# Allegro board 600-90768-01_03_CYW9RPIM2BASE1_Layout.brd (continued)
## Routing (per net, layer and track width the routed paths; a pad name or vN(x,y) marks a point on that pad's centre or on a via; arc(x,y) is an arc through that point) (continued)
GND_EARTH: length 100.7
  BOTTOM w0.381: J47.SH3 44.82,85.98 ; J47.SH3 43.01,85.98 ; J47.SH3 43.91,87.39 ; J47.SH3 43.91,84.57 ; J3.SH2 70.69,77.65 ; J3.SH2 70.69,73.44 ; J3.SH2 72.8,75.55 ; J3.SH2 68.58,75.55 ; J3.SH4 70.69,83.25 ; J3.SH4 72.8,81.15 ; J3.SH4 68.58,81.15 ; J3.SH4 70.69,79.04 ; 115.11,83.16 115.11,84.39 ; 115.11,83.16 J1.SH2 ; 115.11,83.16 114.05,84.23 ; 35.17,84.39 J47.SH2 34.71,84.39 ; 31.57,88.26 C180.2 32.12,87.73 ; 43.91,84.39 J47.SH1 44.82,84.39 ; J47.SH4 35.62,85.98 ; J47.SH4 34.71,84.57 ; J47.SH4 33.81,85.98 ; J47.SH4 34.71,87.39 ; 49.35,75.55 J4.SH2 ; J4.SH2 53.56,75.55 ; J4.SH2 51.46,77.65 ; 32.12,86.72 R372.2 31.57,86.19 ; 49.35,81.15 J4.SH4 ; J4.SH4 53.56,81.15 ; J4.SH4 51.46,79.04 ; J4.SH4 51.46,83.25 ; J1.SH3 124.31,87.39 ; J1.SH3 123.4,85.98 ; J1.SH3 125.22,85.98 ; J1.SH3 124.31,84.57 ; 123.4,82.98 J1.SH1 ; J1.SH1 124.31,81.57 ; J1.SH1 125.22,82.98 ; J1.SH1 124.31,84.39 ; 65.56,73.44 J4.SH1 ; J4.SH1 65.56,77.65 ; J4.SH1 63.45,75.55 ; J4.SH1 67.66,75.55 ; 115.11,84.57 J1.SH4 ; J1.SH4 114.2,85.98 ; J1.SH4 116.02,85.98 ; J1.SH4 115.11,87.39 ; J3.SH3 86.9,81.15 ; J3.SH3 84.79,83.25 ; J3.SH3 82.68,81.15 ; J3.SH3 84.79,79.04 ; J3.SH1 84.79,77.65 ; J3.SH1 82.68,75.55 ; J3.SH1 86.9,75.55 ; 63.45,81.15 J4.SH3 ; J4.SH3 67.66,81.15 ; J4.SH3 65.56,79.04 ; J4.SH3 65.56,83.25 ; J1.SH2 116.02,84.39 ; J1.SH2 114.2,84.39
V3P3: length 20.1
  TOP w0.305: U29.23 38.77,71.84 38.75,71.86 C165.1 C173.1 36.17,71.86 36.17,71.87 C162.1
  TOP w0.381: R359.1 v1(27.05,71.55) ; C162.1 v1(34.33,71.87) 34.33,70.82 R347.1 ; R367.1 R365.1 v1(30.42,73.07) ; R369.1 v1(27.06,73.06)
  BOTTOM w0.381: v1(27.05,71.55) 27.05,73.05 v1(27.06,73.06) 27.07,73.07 v1(30.42,73.07) 31.62,71.87 v1(34.33,71.87)
VBAT: length 54.3
  TOP w0.305: J23.4 46.87,39.48 v1(46.71,39.65) 46.37,39.31 J23.2 ; J23.72 63.87,39.21 v1(63.99,39.33) 64.37,38.95 J23.74
  L03_PWR w0.508: J21.2 84.18,30.18 82.28,32.07 76.35,32.07 70.8,37.63 65.69,37.63 v1(63.99,39.33) 63.25,40.07 47.13,40.07 v1(46.71,39.65)
VBUS: length 49.3
  L03_PWR w0.508: J3.5 81.24,80.46 77.57,84.12 64.1,84.12 62.01,82.03 J4.5 J4.1
  BOTTOM w0.508: J3.5 J3.1 81.24,73.28 81.68,72.85 U2.6 82.74,66.98 82.74,66.98 C2.1 84.05,66.95 C6.1 C5.1 C4.1 C3.1
VBUS_FET_EN: length 39.8
  TOP w0.127: R297.2 v1(25.55,49.76) ; v1(37.49,68.07) 38.43,67.13 38.43,62.74 TP32.1 30.86,61.72 30.12,60.99 30.12,54.28 31.65,52.76 v1(31.65,52.15) ; v1(38.85,68.59) 38.86,68.58 38.86,68.01 39.05,67.82 39.85,67.82 40.13,68.1 40.13,68.48 40.67,69.01 40.67,69.44 41.18,69.96 U29.3
  BOTTOM w0.127: v1(25.55,49.76) 26.26,49.05 29.6,49.05 31.65,51.1 v1(31.65,52.15) ; v1(38.85,68.59) 38.32,68.07 v1(37.49,68.07)
VBUS_MAX: length 11.1
  TOP w0.127: R367.2 R366.2 32.74,69.32 32.99,69.06 39.27,69.06 40.19,69.99 40.42,69.99 40.68,70.24 U29.2
VBUS_MIN: length 12.7
  TOP w0.127: R364.2 R365.2 33.58,72.22 33.58,69.57 33.83,69.32 39.09,69.32 40.18,70.4 U29.1
VBUS_OUT: length 24.4
  TOP w0.305: U29.11 v1(44.36,73.34)
  TOP w0.381: 20.8,54.51 U35.6 23.14,54.51 ; 25.06,50.48 C139.1 ; C139.1 25.71,51.21 ; C139.1 25.06,51.94 ; 21.97,52.6 U35.5 ; U35.5 23.14,53.24 ; U35.5 20.8,53.24
  BOTTOM w0.305: v1(41.96,68.33) 42.32,68.33 44.36,70.37 v1(44.36,73.34)
  BOTTOM w0.381: C29.1 30.63,31.36 ; C29.1 29.85,30.38 ; C29.1 29.85,32.34 ; R390.1 41.75,66.89 ; R390.1 39.79,66.89 ; R390.1 40.77,67.82 ; C28.1 30.63,29.25 ; C28.1 29.85,28.27 ; C28.1 29.85,30.23
  BOTTOM w0.635: U12.2 30.88,27.58
  vias: v1(26.77,50.57) v1(27.36,51.26) v1(27.91,50.6) v1(28.52,51.26) v1(29.13,50.6) v1(31.22,31.19) v1(31.22,30.18) v1(31.22,29.16) v1(32.11,30.68) v1(32.11,29.67) v1(39.42,67.23) v1(39.57,68.33) v1(40.11,69.09) v1(40.77,68.33) v1(41.35,69.11) v1(42.39,67.23)
VCCD: length 2.7
  TOP w0.305: C175.1 37.81,70.08 39.01,70.08 39.43,70.49 U29.24
VCCD_17758174: length 2.5
  BOTTOM w0.305: C61.1 30.94,82.16 U16.12
  BOTTOM w0.381: C61.1 R94.1
VDD_5V: length 146.5
  TOP w0.203: J10.79 105.77,32.14 105.69,32.06 105.29,32.06 v1(105.01,32.06) ; J10.77 105.53,32.54 v1(105.46,32.61) ; v1(105.01,31.11) 105.29,31.11 105.69,31.11 105.69,31.11 105.96,31.11 106.19,31.34 J10.83 ; J10.81 106.12,31.74 105.97,31.59 v1(105.49,31.59) ; J10.85 106.28,30.94 105.97,30.63 v1(105.49,30.63) ; v1(105.01,30.15) 105.29,30.15 105.69,30.15 105.69,30.15 105.96,30.15 106.35,30.54 J10.87
  TOP w0.508: v1(47.78,61.72) 49.61,61.72 v1(51.44,59.89)
  L03_PWR w0.381: v1(47.96,67.01) 47.94,67.01 47.4,67.55 47.4,73.91 46.3,75.01 46.3,85.5 44.5,87.3 32.92,87.3 31.36,85.74 31.36,83.4 30.15,82.19 29.52,82.19 28.14,80.82 27.43,80.82 v1(26.57,79.96)
  L03_PWR w0.508: v1(105.01,32.06) 103.6,33.48 102.01,33.48 101.42,34.06 101.42,35.89 101.73,36.2 101.73,37.94 99.51,40.16 98.7,40.16 93.3,45.57 87.66,45.57 87.13,45.04 86.61,45.04 84.42,47.22 74.93,47.22 74.19,46.48 72.52,46.48 69.88,49.12 60.71,49.12 60.01,48.43 55.71,48.43 52.58,51.56 52.58,58.75 v1(51.44,59.89)
  BOTTOM w0.305: U16.15 27.66,79.89 C59.1
  BOTTOM w0.381: R383.2 46.43,63.07 ; R383.2 45.5,64.05 ; R383.2 45.5,62.09 ; R405.1 48.37,64.05 ; R405.1 47.45,63.07 ; R405.1 48.37,62.09 ; v1(26.57,79.96) 26.57,79.25 26.95,78.87 C60.1 C59.1
VDD_REG_5V: length 9.1
  BOTTOM w0.381: D28.A 22.22,60.78 ; D28.A 21.24,59.45 ; D28.A 20.26,60.78 ; D28.A 21.24,62.11 ; R405.2 50.28,64.05 ; R405.2 51.21,63.07 ; R405.2 50.28,62.09 ; 17.39,60.25 R393.2 ; R393.2 17.95,60.78 ; R393.2 17.39,61.31
  vias: v1(18.62,60.96) v1(18.62,59.39) v1(19.1,60.17) v1(19.58,60.96) v1(19.61,59.39) v1(51.79,64.16) v1(51.77,63.04) v1(51.79,61.98) v1(52.55,63.63) v1(52.55,62.54)
VDDD: length 22.1
  BOTTOM w0.305: U16.24 23.9,84.66 R407.1
  BOTTOM w0.381: R94.2 31.95,80.26 C62.1 C63.1 ; R407.1 R80.1
  BOTTOM w0.508: R80.1 22.58,84.51 22.58,83.46 24.74,81.31 24.74,78.28 26.46,76.56 30.92,76.56 32,77.64 C63.1
VDDIO: length 37.2
  TOP w0.254: v1(62.99,34.18) 61.87,35.3 J23.64
  L03_PWR w0.508: J36.2 86.69,25.22 85.83,24.36 v1(82.5,24.36)
  BOTTOM w0.508: v1(82.5,24.36) 81.74,25.12 71.3,25.12 69.75,26.67 68.45,26.67 62.99,32.13 v1(62.99,34.18)
BT_DBG_CTS: length 77.5
  TOP w0.127: J37.5 3.1,67.48 7.44,63.14 7.44,54.56 13.54,48.46 37.48,48.46 43.7,42.25 47.03,42.25 47.21,42.06 60.78,42.06 62.62,43.9 J23.67
BT_DBG_RTS: length 74.9
  TOP w0.127: J23.65 62.12,43.86 60.58,42.32 47.32,42.32 47.13,42.5 43.83,42.5 37.58,48.74 33.35,48.74 27.66,54.43 27.66,58.11 26,59.77 22.15,59.77 19.42,62.5 13.73,62.5 9.41,66.82 6.3,66.82 J37.4
BT_DBG_RX: length 91.8
  TOP w0.127: R53.1 69.14,36.18 69.14,40.28 69.67,40.82 69.67,42.85 67.89,44.63 67.89,45.97 67.28,46.58 64.26,46.58 64.12,46.44 J23.73 64.12,43.07 62.61,41.55 47,41.55 46.82,41.74 43.48,41.74 37.27,47.96 13.33,47.96 6.93,54.35 6.93,57.48 5.03,59.39 5.03,61.8 4.42,62.4 J37.7
BT_DBG_TX: length 101.1
  TOP w0.127: v1(76.94,45.87) 75.18,47.63 64.29,47.63 63.62,46.96 J23.71 63.62,43.15 62.28,41.81 47.11,41.81 46.92,41.99 43.59,41.99 37.37,48.21 13.43,48.21 7.19,54.45 7.19,57.81 5.49,59.51 5.49,62.56 3.1,64.94 J37.6
  L04 w0.127: v1(76.94,45.87) 77.44,45.36 79.65,45.36 81.08,43.94 82.52,43.94 v1(83.46,43)
  BOTTOM w0.127: v1(83.46,43) R88.1
BT_HOST_WAKE: length 134.3
  TOP w0.127: v1(94.31,38.2) 94.11,38 94.11,29.67 94.77,29.01 94.77,21.54 98.88,17.42 98.88,16 97.59,14.71 95.81,14.71 95.43,15.08 U10.5 ; v1(48.77,34.24) 49.38,34.24 v1(49.83,33.78) ; v1(82.17,38.15) 81.33,37.31 81.33,33.45 79.78,31.9 76.99,31.9 76.17,31.09 v1(76.17,28.5)
  BOTTOM w0.127: v1(49.83,33.78) 50.95,33.78 54.51,37.34 65.01,37.34 73.85,28.5 v1(76.17,28.5) ; v1(94.31,38.2) 93.88,38.2 93.42,38.66 89.48,38.66 88.29,37.47 85.17,37.47 84.31,38.33 R86.2 83.45,38.33 83.27,38.15 v1(82.17,38.15) ; J35.6 18.26,47.73 30,47.73 30.53,47.19 30.53,41.57 32.09,40.02 32.09,37.71 36.65,33.15 47.68,33.15 v1(48.77,34.24)
BT_HOST_WAKE_3P3: length 54.3
  TOP w0.127: J23.20 50.87,35.36 57.65,28.57 72.49,28.57 v1(72.62,28.7) ; v1(89.2,15.28) 89.46,15.54 R34.2
  BOTTOM w0.127: v1(72.62,28.7) 73.51,27.81 83.47,27.81 84.99,26.29 84.99,19.5 v1(89.2,15.28)
BT_NDIS: length 23.2
  TOP w0.127: v1(103.45,10.77) SW8.4 ; v1(106.6,24.92) 108.37,26.68 108.37,29.5 108.13,29.74 J10.91
  BOTTOM w0.127: v1(103.45,10.77) 103.2,11.02 103.2,20.88 106.6,24.28 v1(106.6,24.92)
BT_REG_ON_3P3: length 131.2
  TOP w0.127: SW2.4 SW2.3 38.18,27.22 39.14,26.26 v1(59.37,26.26) 65.15,26.26 67.89,23.52 67.89,16.97 69.2,15.67 81.13,15.67 81.51,15.29 84.53,15.29 85.32,14.5 ; R33.2 90.04,14.51 R25.2 88.46,14.5 85.32,14.5 ; SW8.8 98.37,7.34 96.85,5.82 90.91,5.82 85.32,11.4 85.32,14.5 ; v1(60.58,34.42) 60.33,34.67 60.33,35.18 59.98,35.52 59.98,36.33 59.37,36.94 J23.54
  BOTTOM w0.127: v1(59.37,26.26) 59.37,32.04 60.4,33.07 60.4,34.24 v1(60.58,34.42)
BT_USB_DN: length 73.9
  TOP w0.127: J1.A7 119.46,80.51 119.58,80.39 119.58,79.62 119.58,79.62 119.58,78.62 v1(119.29,78.33) 119.29,78.32 119.58,78.04 119.58,77.86 U34.2
  L04 w0.107: v1(72.95,73.13) 73.23,72.85 73.71,72.85 74.42,73.56 80.98,73.56 82.55,71.98 90.12,71.98 91.26,70.84 105.63,70.84 111.98,77.19 119.26,77.19 119.58,77.51 119.58,78.04 v1(119.29,78.33)
  BOTTOM w0.127: v1(72.95,73.13) 72.67,72.85 72.24,72.85 71.78,72.39 71.78,68.05 72.57,67.26 73.41,67.26 73.77,66.9 73.77,66.15 73.76,66.14 73.76,66.07 73.64,65.95 U1.8 ; v1(119.29,78.33) 119.58,78.04 119.58,77.83 119.43,77.67 118.24,77.67 117.96,77.96 117.96,79.63 119.01,80.69 119.19,80.69 119.42,80.46 119.6,80.46 119.78,80.64 119.78,80.82 119.55,81.04 119.55,81.22 119.84,81.51 119.84,81.96 J1.B7
BT_USB_DP: length 73.9
  TOP w0.127: U34.1 119.84,77.86 119.84,78.04 120.13,78.32 v1(120.13,78.33) 119.84,78.62 119.84,79.51 119.84,80.39 119.96,80.51 J1.A6
  L04 w0.107: v1(120.13,78.33) 119.84,78.04 119.84,77.4 119.37,76.93 112.08,76.93 105.73,70.58 91.15,70.58 90.01,71.72 82.44,71.72 80.87,73.3 74.53,73.3 73.82,72.59 73.23,72.59 v1(72.95,72.31)
  BOTTOM w0.127: U1.9 74.14,65.94 74.02,66.06 74.02,67 73.52,67.51 72.67,67.51 72.03,68.15 72.03,72.28 72.34,72.59 72.67,72.59 v1(72.95,72.31) ; v1(120.13,78.33) 119.84,78.04 119.84,77.72 119.53,77.42 118.14,77.42 117.7,77.85 117.7,79.73 119.58,81.61 119.58,81.96 J1.B6
CC1: length 14.8
  TOP w0.14: U29.15 41.68,76.09 D18.K 41.59,76.29 42.24,76.94 42.85,76.94 44.93,79.02 v1(44.93,79.35) 41.4,79.35 40.62,80.13 40.31,80.13 40.18,80.27 40.18,80.58 40.06,80.69 J47.A5
  BOTTOM w0.14: C158.1 45.93,79.68 45.59,79.35 v1(44.93,79.35)
CC2: length 26
  TOP w0.14: U29.14 42.18,75.56 D24.K 42.79,76.29 46,79.5 46,81.2 45.24,81.97 v1(45.24,82.35)
  L04 w0.112: J47.B5 38.51,86.7 39.4,87.58 44.5,87.58 45.24,86.84 v1(45.24,82.35)
  BOTTOM w0.14: v1(45.24,82.35) C159.1
CTS: length 125.6
  TOP w0.127: R98.2 v1(71.52,33.55)
  L04 w0.127: v1(71.52,33.55) 71.52,30.15 70.99,29.62 69.7,29.62 68.26,28.17 41.91,28.17 40.74,27 36.22,27 35.43,26.22 28.88,26.22 27.84,27.26 15.73,27.26 12.79,30.2 12.79,59.22 20.15,66.58 20.15,67.98 20.25,68.07 20.25,75.47 23.09,78.31 23.09,81.15 23.93,82 v1(23.93,83.66)
  BOTTOM w0.14: U16.22 v1(23.93,83.66)
EEPROM_NWP: length 57.7
  TOP w0.127: J10.20 110.84,44.14 110.99,44.3 112.73,44.3 v1(113.13,43.89) ; v1(118.57,43.03) 118.57,36.64 117.6,35.67 117.6,26.97 v1(113.46,22.83) ; SW8.6 v1(100.91,8.28)
  BOTTOM w0.127: v1(100.91,8.28) 107.52,8.28 108.69,9.45 111.35,9.45 112.62,10.72 112.62,12.78 113.46,13.61 v1(113.46,22.83) ; v1(118.57,43.03) 117.98,43.61 117.04,43.61 116.76,43.89 v1(113.13,43.89)
ETH_LEDG: length 37
  TOP w0.127: R14.1 90.11,67.47 90.3,67.28 90.53,67.28 91.16,66.65 v1(91.54,66.65) ; J10.15 106.66,44.94 106.61,44.89 105.99,44.89 105.64,45.24 105.03,45.24 103.04,47.23 103.04,49.54 95.33,57.25 v1(95.33,57.58)
  BOTTOM w0.127: v1(91.54,66.65) 91.42,66.77 91.42,68.03 91.69,68.3 92.71,68.3 93.2,67.81 93.2,67.03 92.94,66.77 92.39,66.77 92.26,66.64 92.26,63.57 95.07,60.76 95.07,57.84 v1(95.33,57.58)
ETH_LEDY: length 32.1
  TOP w0.127: R13.1 91.05,67.47 91.4,67.13 v1(92,67.13) ; v1(94.82,56.85) 95.28,56.85 102.78,49.34 102.78,47.13 104.92,44.99 105.53,44.99 105.9,44.62 106.71,44.62 106.79,44.54 J10.17
  BOTTOM w0.127: v1(92,67.13) 92,63.52 92.01,63.52 92.01,63.46 94.82,60.65 v1(94.82,56.85)
EXT_5V: length 23.3
  BOTTOM w0.381: 18.74,73.24 D30.C ; D30.C 20.37,74.32 ; D30.C 18.74,75.4 ; 16.38,79.64 J48.1 ; J48.1 18.88,80.9 ; J48.1 18.88,78.38 ; J48.1 21.39,79.64 ; D31.C 18.89,71.13 ; D31.C 20.42,69.8 ; D31.C 18.89,68.47 ; D31.C 17.36,69.8 ; D27.A 22.22,65.23 ; D27.A 21.24,66.56 ; D27.A 20.26,65.23 ; D27.A 21.24,63.9 ; 17.39,64.7 R394.2 ; R394.2 17.39,65.76 ; R394.2 17.95,65.23
EXT_LPO: length 56.5
  TOP w0.127: U11.2 71.66,43.02 73.61,41.07 73.61,32.46 71.53,30.38 v1(70.74,30.38) ; U10.6 95.29,15.58 95.84,15.04 97.54,15.04 98.55,16.05 98.55,17.37 95.22,20.7 90.25,20.7 88.27,22.68 88.27,25.17 86.82,26.62 83.97,26.62 v1(83.31,27.28)
  BOTTOM w0.127: v1(70.74,30.38) 70.74,29.96 73.22,27.48 83.11,27.48 v1(83.31,27.28)
EXT_LPO_3P3: length 32.5
  TOP w0.127: U10.11 91.86,15.58 90.72,16.72 90.72,19.84 88.01,22.56 88.01,25.07 86.71,26.37 83.57,26.37 v1(83.53,26.4) ; R48.1 v1(70.02,30.29)
  BOTTOM w0.127: v1(83.53,26.4) 82.7,27.23 73.08,27.23 v1(70.02,30.29)
FAULT: length 19.1
  TOP w0.127: TP31.1 41.25,60.38 41.25,62.99 45.03,66.78 45.03,72.26 v1(44.95,72.34) U29.9
  BOTTOM w0.127: v1(44.95,72.34) 45.83,72.34 Q14.G 45.83,73.51 R374.2
FET_GATE: length 11
  TOP w0.127: R321.2 13.61,53.23 12.95,52.58 D25.A ; R321.2 R298.2 14.76,54.05 v1(15.44,54.05) ; R321.2 17.29,53.23 U35.4 ; v1(15.44,55.45) 15.77,55.78 U35.2
  BOTTOM w0.127: v1(15.44,54.05) v1(15.44,55.45)
FET_SRC: length 10.5
  TOP w0.127: U35.3 17.24,54.56 15.95,54.56 15.58,54.93 R298.1 ; R298.1 14.73,54.94 13.28,54.94 12.6,55.63 D25.C ; R298.1 14.73,56.39 15.39,57.05 U35.1
FLIP: length 29.8
  TOP w0.127: v1(35.26,70.69) 35.26,69.98 35.11,69.83 R347.2 ; U29.10 44.88,72.84 v1(45.03,73) 45.67,72.36 45.67,66.7 42.6,63.63 TP35.1
  BOTTOM w0.127: v1(35.26,70.69) 35.48,70.46 42.82,70.46 43.46,71.09 43.46,73.53 43.87,73.94 44.7,73.94 45.03,73.61 v1(45.03,73)
GLOBAL_EN: length 21.7
  TOP w0.127: J10.99 v1(107.51,26.99) ; SW8.1 v1(107.26,10.97)
  BOTTOM w0.127: v1(107.26,10.97) 105.54,12.7 105.54,18.44 109.4,22.3 109.4,25.11 v1(107.51,26.99)
GPIO2: length 42.1
  TOP w0.127: v1(115.62,33.3) 112.24,36.68 111.13,36.68 111,36.54 J10.58 ; v1(116.71,33.07) 116.43,32.79 116.43,27.64 110.85,22.05 103.81,22.05 100.28,18.52 100.28,16.61 97.75,14.08 U10.3
  L04 w0.127: v1(115.62,33.3) 115.85,33.07 v1(116.71,33.07)
GPIO3: length 41.5
  TOP w0.127: U10.4 95.35,14.58 95.55,14.38 97.68,14.38 99.97,16.67 99.97,18.69 103.63,22.35 110.76,22.35 116.15,27.75 116.15,33.71 112.92,36.94 J10.56
GPIO4: length 98.8
  TOP w0.127: TP38.1 99.24,43.71 99.24,36.04 v1(99.92,35.36) ; J23.42 v1(56.37,36.8) ; J10.54 113.81,37.34 v1(113.94,37.21)
  L04 w0.127: v1(113.94,37.21) 113.54,36.8 111.28,36.8 110.77,36.3 110.77,31.17 106.78,27.18 v1(103.63,27.18)
  BOTTOM w0.127: v1(103.63,27.18) 103.25,26.8 101.6,26.8 101.16,27.24 97.15,27.24 96.62,27.76 84.71,27.76 84.41,28.06 73.93,28.06 64.91,37.08 56.65,37.08 v1(56.37,36.8) ; v1(99.92,35.36) 100.38,35.36 100.53,35.51 104.44,35.51 104.78,35.84 104.78,36.24 105.13,36.6 107.87,36.6 108.23,36.96 113.69,36.96 v1(113.94,37.21)
GPIO5: length 96.1
  TOP w0.127: R37.2 52.09,49.06 51.89,49.27 51.89,52.62 53.29,54.03 54.74,54.03 55.61,53.16 63.21,53.16 63.83,53.77 63.83,55.07 64.08,55.31 64.08,57.58 64.67,58.17 71.65,58.17 72.14,57.68 75.26,57.68 v1(75.44,57.51) ; v1(117.14,54.97) 117.14,44.63 113.86,41.34 J10.34
  BOTTOM w0.127: v1(75.44,57.51) 75.44,57.15 77.6,54.99 90.88,54.99 92.25,53.62 102.74,53.62 103.99,54.86 114.68,54.86 115.17,55.35 116.35,55.35 116.74,54.97 v1(117.14,54.97)
GPIO6: length 52.4
  TOP w0.14: v1(116.36,56.67) 116.13,56.44 116.13,44.98 113.56,42.42 111.43,42.42 111.15,42.14 J10.30
  BOTTOM w0.14: U15.3 85.23,59.11 85.98,59.11 88.9,56.18 91.85,56.18 92.74,55.3 102.39,55.3 104.04,56.95 116.08,56.95 v1(116.36,56.67)
GPIO6_3P3: length 33.1
  TOP w0.14: v1(77.77,58.19) 77.77,57.61 75.24,55.07 75.24,52.41 72.61,49.78 66.86,49.78 66.02,50.62 61.54,50.62 60.99,50.06 60.99,49.42 R51.2
  L04 w0.112: v1(85.88,57.33) 85.01,58.19 v1(77.77,58.19)
  BOTTOM w0.14: v1(85.88,57.33) 85.23,57.33 U15.4
GPIO7: length 60
  TOP w0.127: v1(103.4,42.16) 104.17,41.4 105.94,41.4 106.8,40.54 J10.37 ; R39.2 53.33,48.6 53.49,48.44 v1(53.49,47.14)
  BOTTOM w0.127: v1(53.49,47.14) 53.75,47.4 54.2,47.4 56.76,44.84 64.89,44.84 65.33,44.4 67.52,44.4 68.38,43.54 71.15,43.54 72.97,41.71 74.74,41.71 74.74,41.71 75.06,41.71 75.07,41.71 82.96,41.71 83.7,42.45 88.68,42.45 89.41,41.73 94.42,41.73 94.42,41.73 96.29,41.73 96.92,42.37 103.2,42.37 v1(103.4,42.16)
GPIO8: length 30.5
  TOP w0.14: J10.39 106.83,40.14 106,40.97 103.68,40.97 v1(103.05,41.61) ; v1(88.16,42.98) v1(88.16,41.81)
  BOTTOM w0.14: v1(103.05,41.61) 104.5,41.61 104.9,42.01 104.9,43 104.47,43.43 103.73,43.43 103.07,44.09 92.25,44.09 91.95,43.79 91.16,43.79 90.86,44.09 89.28,44.09 v1(88.16,42.98) ; v1(88.16,41.81) 87.93,42.04 85.67,42.04 R57.1
GPIO9: length 59
  TOP w0.14: J10.40 110.81,40.14 110.98,39.98 112.88,39.98 113.58,39.27 v1(113.58,38.66) ; R55.1 v1(70,34.3)
  L04 w0.112: v1(113.58,38.66) 113.58,38.48 112.62,37.51 110.82,37.51 110.09,36.78 110.09,31.5 106.91,28.32 103.15,28.32 v1(102.92,28.09)
  BOTTOM w0.14: v1(70,34.3) 70.02,34.3 74.15,30.16 75.83,30.16 77.15,28.84 84.77,28.84 85.2,28.41 97.19,28.41 97.73,27.88 102.7,27.88 v1(102.92,28.09)
GPIO10: length 61.2
  TOP w0.127: J10.44 110.82,39.34 110.91,39.43 112.64,39.43 v1(113.03,39.04) ; R53.2 70,35.73 69.82,35.56 v1(68.55,35.56)
  L04 w0.127: v1(102.18,28.6) 102.31,28.73 106.45,28.73 109.7,31.98 109.7,36.92 110.66,37.88 112.46,37.88 113.03,38.45 v1(113.03,39.04)
  BOTTOM w0.127: v1(102.18,28.6) 101.85,28.27 97.97,28.27 97.43,28.81 85.37,28.81 84.94,29.24 77.32,29.24 75.99,30.56 74.44,30.56 72.87,32.13 72.87,33.86 72.62,34.11 71.5,34.11 70.05,35.56 v1(68.55,35.56)
GPIO11: length 60.5
  TOP w0.127: J10.38 113.66,40.54 114.04,40.16 v1(114.04,39.19) ; R54.1 70,33 70.18,32.82 v1(70.79,32.82)
  L04 w0.127: v1(114.04,39.19) 114.04,38.22 112.95,37.13 110.97,37.13 110.46,36.63 110.46,31.34 106.91,27.79 103.33,27.79 v1(102.95,27.41)
  BOTTOM w0.127: v1(70.79,32.82) 73.84,29.77 75.67,29.77 76.99,28.45 84.61,28.45 85.04,28.02 96.98,28.02 97.5,27.49 102.86,27.49 v1(102.95,27.41)
GPIO12: length 27.5
  TOP w0.127: v1(94.23,42.16) v1(94.23,38.91) ; J10.31 106.87,41.74 106.06,42.56 105.65,42.56 105.02,43.18 104.04,43.18 v1(103.76,42.9)
  BOTTOM w0.127: v1(94.23,42.16) 96.32,42.16 96.82,42.67 103.53,42.67 v1(103.76,42.9) ; v1(94.23,38.91) 89.31,38.91 88.95,39.27 85.47,39.27 85.17,38.96 85.17,38.34 R87.1
GPIO13: length 66
  TOP w0.127: J10.28 111.02,42.54 111.15,42.67 111.32,42.67 111.32,42.68 113.19,42.68 115.67,45.16 v1(115.67,54.91) ; v1(85.16,43.76) 85.16,45.83 84.89,46.1 84.89,52.07 82.8,54.15 v1(81.2,54.15)
  BOTTOM w0.127: v1(85.16,43.76) R89.2 ; v1(81.2,54.15) 82.17,54.15 82.68,54.66 90.6,54.66 91.97,53.29 103,53.29 104.32,54.61 115.37,54.61 v1(115.67,54.91)
GPIO14: length 32.2
  TOP w0.127: v1(102.46,40.26) 102.41,40.21 102.41,39.12 104.5,37.03 106.13,37.03 106.14,37.02 106.15,37.02 106.23,36.94 J10.55
  BOTTOM w0.127: v1(102.46,40.26) 101.88,39.67 97.08,39.67 93.98,36.58 80.45,36.58 J30.3
GPIO15: length 32.6
  TOP w0.127: J10.51 106.3,37.74 106.08,37.97 103.97,37.97 102.69,39.24 102.69,39.83 103.12,40.26 v1(103.12,40.31)
  BOTTOM w0.127: J30.1 80.53,36.27 94.11,36.27 97.26,39.42 102.29,39.42 103.12,40.26 v1(103.12,40.31)
GPIO16: length 30.7
  TOP w0.127: v1(102.23,41.55) 102.23,42.04 103.65,43.46 105.12,43.46 105.75,42.82 106.17,42.82 106.85,42.14 J10.29
  BOTTOM w0.127: J30.5 80.96,40.2 81.13,40.03 86.84,40.03 88.01,41.2 96.6,41.2 97.26,41.86 101.93,41.86 v1(102.23,41.55)
GPIO17: length 51.2
  TOP w0.127: v1(117.54,42.61) 117.54,42.56 114.99,40.01 114.99,38.81 113.92,37.74 111.2,37.74 110.8,38.14 J10.50
  BOTTOM w0.127: v1(117.54,42.61) 116.71,43.44 112.8,43.44 111.96,44.28 105.9,44.28 105.44,43.82 104.06,43.82 103.33,44.55 97.66,44.55 96.95,45.26 93.93,45.26 93.68,45.52 87.94,45.52 87.58,45.16 84.25,45.16 82.73,43.64 81.41,43.64 80.51,42.74 J30.7
GPIO18: length 17.7
  TOP w0.127: J10.49 106.29,38.14 106.18,38.25 104.22,38.25 103.17,39.29 v1(103.17,39.65)
  BOTTOM w0.127: J25.1 93.92,35.12 94.13,35.33 94.13,35.83 97.42,39.12 102.64,39.12 v1(103.17,39.65)
GPIO19: length 24.3
  TOP w0.127: J10.26 111.78,42.94 111.96,43.13 v1(111.96,43.48)
  BOTTOM w0.127: J25.3 94.63,37.66 96.9,39.93 101.42,39.93 102.39,40.89 104.34,40.89 107.47,44.02 111.42,44.02 v1(111.96,43.48)
GPIO20: length 17.1
  TOP w0.127: v1(101.47,41.42) 101.47,42.01 102.21,42.75 102.54,42.75 103.5,43.71 105.22,43.71 105.85,43.09 106.27,43.09 106.81,42.54 J10.27
  BOTTOM w0.127: v1(101.47,41.42) 101.37,41.53 97.31,41.53 96.67,40.89 93.5,40.89 J25.5
GPIO21: length 15.7
  TOP w0.127: v1(102.72,43.56) 103.12,43.96 105.33,43.96 105.95,43.34 106.37,43.34 106.78,42.94 J10.25
  BOTTOM w0.127: J25.7 93.76,43.69 102.59,43.69 v1(102.72,43.56)
GPIO22: length 78
  TOP w0.14: J10.46 v1(111.18,38.94) ; R28.2 v1(47.02,49.25)
  L05 w0.102: v1(111.18,38.94) 109.5,38.94 109.02,38.46 106.05,38.46 104.42,36.83 98.77,36.83 93.69,31.75 93.68,31.75 93.63,31.7 93.61,31.7 93.56,31.65 93.55,31.65 93.52,31.62 76.25,31.62 69.52,38.35 59.15,38.35 59.04,38.25 59.04,37.9 58.94,37.8 58.66,37.8 58.56,37.9 58.56,38.25 58.46,38.35 56.39,38.35 47.02,47.73 v1(47.02,49.25)
GPIO23: length 78
  TOP w0.14: v1(48.31,50.34) 48.31,49.78 47.85,49.33 R29.2 ; J10.47 106.39,38.54 106.2,38.73 v1(105.64,38.73)
  L05 w0.102: v1(48.31,50.34) 48.51,50.14 48.51,47.9 54.2,42.21 55.37,42.21 57.2,40.39 57.78,40.39 57.88,40.49 57.88,40.74 57.98,40.84 58.19,40.84 58.29,40.74 58.29,40.49 58.39,40.39 58.59,40.39 58.69,40.49 58.69,40.74 58.8,40.84 59,40.84 59.1,40.74 59.1,40.49 59.2,40.39 59.41,40.39 59.51,40.49 59.51,40.74 59.61,40.84 59.81,40.84 59.91,40.74 59.91,40.49 60.02,40.39 60.22,40.39 60.32,40.49 60.32,40.74 60.42,40.84 60.63,40.84 60.73,40.74 60.73,40.49 60.83,40.39 61.03,40.39 61.13,40.49 61.13,40.69 61.23,40.79 61.44,40.79 61.54,40.69 61.54,40.49 61.64,40.39 62.1,40.39 62.2,40.28 63.3,40.28 63.5,40.49 63.5,41.37 63.5,41.38 63.51,41.38 63.9,41.78 63.91,41.78 63.92,41.78 66.67,41.78 76.53,31.93 93.45,31.93 93.5,31.98 93.51,31.98 93.56,32.03 93.58,32.03 98.77,37.22 104.14,37.22 v1(105.64,38.73)
GPIO24: length 78
  TOP w0.14: v1(48.95,49.25) 48.69,49 R30.2 ; v1(105.92,39.37) 106.05,39.37 106.47,38.94 J10.45
  L05 w0.102: v1(48.95,49.25) 48.97,49.25 48.97,47.93 54.33,42.57 57.96,42.57 58.06,42.47 58.06,41.78 58.16,41.68 58.37,41.68 58.47,41.78 58.47,42.47 58.57,42.57 58.77,42.57 58.87,42.47 58.87,41.78 58.98,41.68 59.18,41.68 59.28,41.78 59.28,42.47 59.38,42.57 59.59,42.57 59.69,42.47 59.69,41.78 59.79,41.68 59.99,41.68 60.09,41.78 60.09,42.47 60.2,42.57 60.4,42.57 60.5,42.47 60.5,41.78 60.6,41.68 60.81,41.68 60.91,41.78 60.91,42.47 61.01,42.57 61.21,42.57 61.31,42.47 61.31,41.78 61.41,41.68 61.62,41.68 61.72,41.78 61.72,42.47 61.82,42.57 66.5,42.57 76.81,32.26 93.4,32.26 93.45,32.31 93.46,32.31 98.72,37.57 103.81,37.57 105.61,39.37 v1(105.92,39.37)
GPIO25: length 78
  TOP w0.14: v1(49.83,49.99) 49.53,49.68 R32.2 ; J10.41 106.77,39.74 106.17,40.34 105.94,40.34 v1(105.87,40.41)
  L05 w0.102: v1(49.83,49.99) 49.83,50.7 49.99,50.85 50.44,50.85 50.55,50.75 50.55,49.49 50.44,49.39 49.68,49.39 49.58,49.29 49.58,49.08 49.68,48.98 50.44,48.98 50.55,48.88 50.55,48.68 50.44,48.57 49.68,48.57 49.58,48.47 49.58,48.27 49.68,48.17 50.44,48.17 50.55,48.07 50.55,47.73 50.65,47.63 50.95,47.63 51.05,47.53 51.05,47.32 50.95,47.22 50.65,47.22 50.55,47.12 50.55,46.75 54.32,42.98 66.62,42.98 77.01,32.59 93.35,32.59 98.76,38 103.63,38 104.75,39.12 104.75,39.83 105.33,40.41 v1(105.87,40.41)
GPIO26: length 78
  TOP w0.14: v1(51.13,49.96) 50.39,49.22 R35.2 ; J10.24 111.17,43.34 111.21,43.38 v1(111.32,43.38)
  L05 w0.102: v1(111.32,43.38) 111.32,42.95 110.95,42.57 110.49,42.57 110.34,42.72 110.34,42.97 110.18,43.13 109.96,43.13 109.8,42.97 109.8,42.67 109.6,42.47 108.2,42.47 106.97,41.24 105.19,41.24 104.04,40.09 104.04,39.29 103.43,38.68 98.52,38.68 97.89,38.05 97.89,38.05 93.02,33.17 77.44,33.17 66.78,43.84 54.42,43.84 52.11,46.15 52.11,49.75 51.77,50.09 51.26,50.09 v1(51.13,49.96)
GPIO27: length 78
  TOP w0.14: J10.48 110.91,38.54 111.1,38.35 111.58,38.35 v1(112.01,38.79) ; v1(51.16,49.26) 51.25,49.16 R36.2
  L05 w0.102: v1(51.16,49.26) 51.48,49.26 51.77,48.97 51.77,47.45 51.56,47.24 51.56,46.22 54.34,43.43 66.73,43.43 77.27,32.89 93.13,32.89 98.17,37.93 98.17,37.94 98.58,38.34 103.52,38.34 104.39,39.22 104.39,39.96 105.33,40.89 106.78,40.89 107.24,40.44 107.47,40.44 107.57,40.34 107.57,40.11 107.67,40.01 107.87,40.01 107.98,40.11 107.98,40.34 108.08,40.44 109.93,40.44 110.39,39.98 111.46,39.98 112.01,39.42 v1(112.01,38.79)
GPIO_VREF: length 14.3
  TOP w0.203: v1(108.74,31.85) 109.43,32.54 J10.78
  TOP w0.381: SW9.2 v1(99.52,26.8)
  L03_PWR w0.381: v1(108.74,31.85) 106.12,29.24 101.93,29.24 99.52,26.82 v1(99.52,26.8)
HD1_M2_N: length 50.4
  TOP w0.127: v1(57.53,58.19) 57.42,58.3 57.24,58.3 53.82,54.89 50.32,54.89 48.72,53.29 48.72,52.27 45.69,49.25 45.69,47.73 47.02,46.41 47.02,45.62 J23.5
  L04 w0.107: v1(57.53,58.19) 57.41,58.32 57.41,58.47 59.26,60.32 59.26,62.93 58.02,64.17 58.02,66.65 60.35,68.98 70.57,68.98 70.78,68.77 72.04,68.77 72.38,68.42 74.05,68.42 74.28,68.19 75.11,68.19 75.33,67.98 v1(75.33,67.91)
  BOTTOM w0.127: R92.1 76.08,68.2 75.62,68.2 v1(75.33,67.91)
HD1_M2_P: length 50.5
  TOP w0.127: v1(56.94,58.78) 56.94,58.37 53.72,55.14 50.21,55.14 48.46,53.39 48.46,52.38 45.44,49.36 45.44,47.62 46.62,46.44 J23.3
  L04 w0.107: v1(75.33,68.75) 75.28,68.7 75.28,68.65 75.08,68.45 74.39,68.45 74.16,68.68 72.49,68.68 72.14,69.03 70.89,69.03 70.68,69.24 60.24,69.24 57.76,66.76 57.76,64.06 59,62.82 59,60.43 57.35,58.78 v1(56.94,58.78)
  BOTTOM w0.127: v1(75.33,68.75) 75.62,68.46 76.12,68.46 R93.1
HD1_N: length 41.1
  L04 w0.107: v1(57.84,61.01) 57.56,61.29 57.56,62.65 56.8,63.41 56.8,67.38 59.61,70.2 70.71,70.2 71.06,69.84 74.24,69.84 74.45,70.05 76.65,70.05 76.99,69.71 76.99,69.26 77.36,68.88 78.64,68.88 78.91,69.15 78.91,69.51 v1(79.2,69.8)
  BOTTOM w0.127: R92.2 77.33,67.88 77.62,68.17 78.24,68.17 78.89,68.83 78.89,69.49 v1(79.2,69.8) 78.9,70.09 78.9,70.32 79.16,70.57 R5.2 ; U14.1 61.37,61.9 61.24,62.03 59.49,62.03 59.23,61.77 57.78,61.77 57.56,61.54 57.56,61.29 v1(57.84,61.01)
HD1_P: length 41.1
  L04 w0.107: v1(78.36,69.8) 78.65,69.51 78.65,69.26 78.53,69.14 77.47,69.14 77.25,69.37 77.25,69.82 76.75,70.31 74.34,70.31 74.13,70.1 71.17,70.1 70.82,70.45 59.5,70.45 56.54,67.49 56.54,63.3 57.3,62.54 57.3,61.29 v1(57.02,61.01)
  BOTTOM w0.127: U14.2 61.36,62.4 61.24,62.28 61.14,62.28 59.38,62.28 59.13,62.03 57.68,62.03 57.3,61.65 57.3,61.29 v1(57.02,61.01) ; R9.1 78.4,70.57 78.65,70.32 78.65,70.09 v1(78.36,69.8) 78.64,69.52 78.64,68.94 78.13,68.43 77.62,68.43 77.31,68.74 R93.2
HD1_PORT_N: length 6.1
  BOTTOM w0.127: R5.1 79.2,72.17 U36.1 79.18,72.28 79.22,72.33 79.22,74.34 78.51,75.05 78.21,75.05 77.88,75.39 77.88,75.79 78,75.92 J3.2
HD1_PORT_P: length 6
  BOTTOM w0.127: J3.3 77.5,75.92 77.62,75.79 77.62,75.29 78.11,74.8 78.41,74.8 78.53,74.67 78.53,74.49 78.31,74.27 78.31,72.35 78.38,72.28 U36.2 78.35,72.17 R9.2
HD2_N: length 46.4
  L04 w0.107: v1(75.94,71.53) 75.79,71.53 75.64,71.37 75.64,71.16 75.57,71.09 75.28,70.8 74.44,70.8 74.02,71.22 70.99,71.22 70.71,71.5 63.32,71.5 63.24,71.42 61.67,71.42 61.11,71.98 60.48,71.98 59.86,71.37 58.9,71.37 55.53,68 55.53,62.03 55.63,61.93 v1(55.8,61.93)
  BOTTOM w0.127: v1(55.8,61.93) 55.65,61.93 55.52,62.05 55.52,62.68 55.86,63.02 61.24,63.02 61.36,62.9 U14.3 ; v1(75.94,71.53) 75.7,71.77 75.7,71.95 U37.1 75.94,72.75 75.98,72.79 75.98,74.36 75.67,74.68 75.67,76.54 76.3,77.17 77.31,77.17 77.88,77.73 77.88,78.49 78,78.62 J3.6
HD2_P: length 46.4
  L04 w0.107: v1(75.13,71.53) 75.25,71.4 75.25,71.16 75.15,71.06 74.55,71.06 74.12,71.48 71.1,71.48 70.82,71.76 63.21,71.76 63.13,71.68 61.78,71.68 61.22,72.24 60.37,72.24 59.76,71.63 58.79,71.63 55.27,68.11 55.27,62.2 v1(54.99,61.93)
  BOTTOM w0.127: U14.4 61.34,63.4 61.22,63.27 55.76,63.27 55.27,62.79 55.27,62.2 v1(54.99,61.93) ; v1(75.13,71.53) 75.38,71.78 75.38,71.96 U37.2 75.14,72.75 75.1,72.79 75.1,74.34 75.1,74.34 75.1,74.35 75.41,74.66 75.41,76.64 76.19,77.42 77.21,77.42 77.62,77.83 77.62,78.46 77.5,78.59 76.77,78.59 J3.7
HD3_N: length 20.6
  BOTTOM w0.127: J4.2 58.96,75.92 58.72,76.15 58.72,77.22 58.37,77.57 56.74,77.57 56.16,76.99 56.16,74.98 56.55,74.58 56.55,73.53 U38.1 56.23,73.2 56.23,71.35 56.54,71.03 56.54,68.53 60.54,64.53 61.2,64.53 61.33,64.4 U14.6
HD3_P: length 20.6
  BOTTOM w0.127: J4.3 57.51,75.77 57.63,75.64 58.34,75.64 58.47,75.77 58.47,77.11 58.26,77.32 56.85,77.32 56.41,76.88 56.41,75.08 56.81,74.69 56.81,73.53 U38.2 57.12,73.21 57.12,71.37 57.11,71.36 57.11,71.35 56.79,71.03 56.79,70.67 56.96,70.5 56.96,70.16 56.79,69.99 56.79,69.65 56.96,69.49 56.96,69.14 56.79,68.98 56.79,68.63 57.66,67.77 57.89,67.77 58.13,67.53 58.13,67.3 58.37,67.05 58.61,67.05 58.85,66.81 58.85,66.58 60.65,64.78 61.2,64.78 61.32,64.9 U14.7
HD4_N: length 20.5
  BOTTOM w0.127: U14.8 61.32,65.4 61.19,65.53 60.74,65.53 59.92,66.35 59.92,69.93 60.71,70.72 60.71,70.98 60.42,71.27 60.42,72.8 60.45,72.84 U39.1 60.45,73.67 60.71,73.92 60.71,79.29 60.26,79.73 58.86,79.73 58.62,79.5 58.62,78.33 58.83,78.13 59.18,78.13 59.51,78.46 J4.6
HD4_P: length 20.6
  BOTTOM w0.127: J4.7 58.24,78.62 58.37,78.75 58.37,79.6 58.75,79.98 60.37,79.98 60.96,79.39 60.96,73.97 61.25,73.67 U39.2 61.25,72.84 61.32,72.78 61.32,71.29 60.96,70.94 60.96,70.61 60.17,69.82 60.17,69.52 60.33,69.37 60.33,69.06 60.17,68.91 60.17,68.48 60.34,68.32 60.34,67.97 60.17,67.81 60.17,67.47 60.34,67.3 60.34,66.96 60.17,66.79 60.17,66.45 60.84,65.78 61.21,65.78 61.33,65.9 U14.9
HDMI0_CEC: length 58.3
  TOP w0.14: J8.13 138.82,78.46 139.12,78.16 139.12,77.5 140.11,76.5 v1(140.11,74.35) ; v1(140.59,71.86) 139.52,70.79 139.04,70.79 137.45,69.2 132.91,69.2 131.11,67.41 131.11,41.53 135.46,37.19 139.57,37.19 140.13,37.74 J5.51
  BOTTOM w0.14: v1(140.59,71.86) 140.59,72.82 140.11,73.3 v1(140.11,74.35)
HDMI0_CK_N: length 68.6
  TOP w0.114: v1(138.96,76.54) 138.63,76.88 138.63,77.16 138.05,77.74 138.05,78.11 138.31,78.38 J8.12 ; J5.90 145.23,30.14 145.96,29.41 146.2,29.41 146.48,29.13 v1(146.51,29.13)
  L05 w0.086: v1(138.96,76.54) 138.7,76.28 138.7,69.2 138.23,68.73 138.23,62.56 144.45,56.34 148.61,56.34 148.61,56.34 148.87,56.34 153.66,51.55 153.66,32.37 150.65,29.36 146.73,29.36 v1(146.51,29.13)
HDMI0_CK_P: length 68.5
  TOP w0.114: J5.88 144.72,30.54 144.84,30.42 145.35,30.42 146.08,29.69 146.2,29.69 146.48,29.97 v1(146.51,29.97) ; J8.10 137.31,78.33 137.41,78.23 137.72,78.23 137.77,78.18 137.77,77.62 138.35,77.05 138.35,76.76 v1(138.13,76.54)
  L05 w0.086: v1(138.13,76.54) 138.39,76.28 138.39,69.33 137.92,68.86 137.92,62.43 144.32,56.03 148.74,56.03 153.35,51.43 153.35,32.5 150.52,29.67 146.62,29.67 146.51,29.78 v1(146.51,29.97)
HDMI0_D0_N: length 68.6
  TOP w0.114: v1(137.08,76.85) 136.71,77.23 136.71,78.27 136.81,78.38 J8.9 ; v1(147.22,30.86) 146.94,31.14 145.65,31.14 145.38,31.42 144.75,31.42 144.68,31.34 J5.84
  L05 w0.086: v1(137.08,76.85) 136.81,76.57 136.81,70.71 134.06,67.97 134.06,66.84 134.15,66.76 134.68,66.76 134.95,66.49 134.95,66.06 134.68,65.8 134.15,65.8 134.06,65.71 134.06,64.29 143.46,54.89 148.49,54.89 152.39,50.99 152.39,34.83 148.69,31.14 147.49,31.14 v1(147.22,30.86)
HDMI0_D0_P: length 68.5
  TOP w0.114: v1(136.25,76.85) 136.43,77.03 136.43,78.15 136.35,78.23 135.96,78.23 135.81,78.38 J8.7 ; v1(147.22,31.7) 146.94,31.42 145.77,31.42 145.49,31.7 144.73,31.7 144.69,31.74 J5.82
  L05 w0.086: v1(147.22,31.7) 147.22,31.55 147.32,31.44 148.56,31.44 152.08,34.96 152.08,50.87 148.36,54.58 143.33,54.58 133.75,64.16 133.75,65.84 134.02,66.1 134.56,66.1 134.64,66.19 134.64,66.36 134.56,66.45 134.02,66.45 133.75,66.71 133.75,68.09 136.5,70.84 136.5,76.6 v1(136.25,76.85)
HDMI0_D1_N: length 68.6
  TOP w0.114: J8.6 135.31,78.38 135.18,78.24 135.18,77.65 134.95,77.42 134.95,77.21 v1(135.23,76.93) ; J5.78 144.88,32.54 144.94,32.6 145.68,32.6 v1(146,32.28)
  L05 w0.086: v1(135.23,76.93) 135.23,76.54 134.96,76.27 134.96,71.46 131.02,67.51 131.02,66.91 131.1,66.82 132.09,66.82 132.36,66.56 132.36,66.13 132.09,65.86 131.1,65.86 131.02,65.77 131.02,65.2 142.65,53.57 148.09,53.57 151.08,50.57 151.08,35.56 148.08,32.56 146.28,32.56 v1(146,32.28)
HDMI0_D1_P: length 68.5
  TOP w0.114: v1(134.39,76.93) 134.67,77.21 134.67,77.54 134.9,77.76 134.9,78.16 134.82,78.23 134.37,78.23 134.31,78.28 J8.4 ; J5.76 144.88,32.94 144.94,32.88 145.76,32.88 v1(146,33.12)
  L05 w0.086: v1(134.39,76.93) 134.39,76.54 134.66,76.27 134.66,71.59 130.71,67.64 130.71,66.78 130.97,66.51 131.97,66.51 132.05,66.43 132.05,66.25 131.97,66.17 130.97,66.17 130.71,65.9 130.71,65.07 142.52,53.26 147.96,53.26 150.77,50.45 150.77,35.69 147.95,32.87 146.25,32.87 v1(146,33.12)
HDMI0_D2_N: length 68.5
  TOP w0.114: J8.3 133.81,78.38 133.6,78.16 133.6,77.94 133.08,77.41 133.08,76.96 v1(133.3,76.74) ; J5.72 144.88,33.74 144.94,33.8 145.51,33.8 145.94,34.23 145.94,35.01 146.12,35.18 146.46,35.18 v1(146.66,34.98)
  L05 w0.086: v1(133.3,76.74) 133.02,76.46 133.02,71.6 129.34,67.92 129.34,67.31 129.07,67.04 128.28,67.04 128.2,66.95 128.2,66.78 128.28,66.69 129.07,66.69 129.34,66.43 129.34,66 129.07,65.73 128.31,65.73 128.22,65.65 128.22,65.47 128.31,65.39 129.07,65.39 129.34,65.12 129.34,64.1 141.16,52.27 147.6,52.27 149.86,50.01 149.86,39.09 148.57,37.8 148.57,35.92 147.88,35.23 146.91,35.23 v1(146.66,34.98)
HDMI0_D2_P: length 68.5
  TOP w0.114: v1(132.46,76.74) 132.8,77.07 132.8,77.53 133.32,78.05 133.32,78.21 133.25,78.28 132.91,78.28 132.81,78.38 J8.1 ; J5.70 144.88,34.14 144.94,34.08 145.4,34.08 145.66,34.35 145.66,35.12 146,35.46 146.46,35.46 146.66,35.66 v1(146.66,35.82)
  L05 w0.086: v1(146.66,35.82) 146.94,35.54 147.75,35.54 148.27,36.05 148.27,37.93 149.56,39.22 149.56,49.89 147.47,51.97 141.03,51.97 129.03,63.97 129.03,64.99 128.94,65.08 128.18,65.08 127.91,65.35 127.91,65.77 128.18,66.04 128.94,66.04 129.03,66.13 129.03,66.3 128.94,66.39 128.16,66.39 127.89,66.65 127.89,67.08 128.16,67.35 128.94,67.35 129.03,67.43 129.03,68.04 132.72,71.73 132.72,76.48 v1(132.46,76.74)
HDMI0_HOTPLUG: length 60.8
  TOP w0.127: v1(142,75.01) 142,78.17 141.82,78.36 J8.19
  TOP w0.14: J5.53 140.29,37.34 139.74,36.79 135.29,36.79 130.72,41.37 130.72,67.6 132.72,69.6 135.97,69.6 137.55,71.18 139.2,71.18 v1(139.88,71.86)
  BOTTOM w0.127: v1(139.88,71.86) 139.88,71.45 140.16,71.17 141,71.17 141.27,71.45 141.27,74.28 v1(142,75.01)
HDMI0_SCL: length 67.6
  TOP w0.14: J8.15 139.82,77.89 v1(139.65,77.72) ; v1(151.16,58.72) 151.76,58.12 151.76,51.56 152.06,51.27 152.06,28.74 151.47,28.16 147.74,28.16 147.73,28.14 J5.100
  BOTTOM w0.14: v1(151.16,58.72) 150.83,59.05 148.77,59.05 146.8,61.02 146.8,67.67 144.88,69.59 144.88,75.18 144.14,75.92 143.26,75.92 142.96,76.22 140.73,76.22 139.65,77.29 v1(139.65,77.72)
HDMI0_SDA: length 76.7
  TOP w0.14: J8.16 140.31,78.07 v1(140.26,78.02) ; v1(152.96,58.01) 152.96,52.55 153.52,51.99 153.52,29.31 151.97,27.76 147.65,27.76 145.65,25.77 141.59,25.77 140.51,26.85 140.51,27.94 140.72,28.14 J5.99
  BOTTOM w0.14: v1(140.26,78.02) 140.26,77.24 140.89,76.61 142.83,76.61 143.18,76.96 143.77,76.96 145.31,75.43 145.31,69.72 147.19,67.83 147.19,61.26 148.97,59.49 151.49,59.49 v1(152.96,58.01)
HDMI_5V: length 6.7
  TOP w0.305: v1(141.38,78.04) 141.31,78.1 J8.18
  BOTTOM w0.508: v1(141.38,78.04) 141.38,80.16 140.86,80.68 C18.1 140.22,80.69 U4.2
ID_SC: length 10.1
  TOP w0.127: TP2.1 102.85,45.1 v1(103.47,45.1) ; J10.35 106.79,40.94 105.87,41.86 104.44,41.86 v1(104.19,42.11)
  L04 w0.127: v1(103.47,45.1) 105.49,43.08 105.49,42.55 105.05,42.11 v1(104.19,42.11)
ID_SD: length 37.5
  TOP w0.127: v1(100.08,36.2) 99.72,36.55 99.72,45.14 98.7,46.15 TP1.1 ; J10.36 115.24,40.94 v1(116.23,41.94)
  BOTTOM w0.127: v1(100.08,36.2) 100.41,36.53 104.7,36.53 105.03,36.86 107.7,36.86 108.05,37.21 113.08,37.21 114.96,39.09 114.96,40.67 v1(116.23,41.94)
ISNK_COARSE: length 23.8
  TOP w0.127: R368.2 R369.2 30.12,72.35 30.12,69.87 30.38,69.61 30.39,69.61 31.22,68.78 38.04,68.78 38.57,68.25 38.57,67.86 38.98,67.44 38.98,67.05 39.46,66.57 42.35,66.57 43.13,67.35 43.13,68.83 42.18,69.79 U29.5
ISNK_FINE: length 21.8
  TOP w0.127: R359.2 R360.2 30.95,68.5 37.96,68.5 38.32,68.15 38.32,67.7 38.73,67.29 38.73,66.95 39.46,66.22 42.62,66.22 43.48,67.08 43.48,69.16 42.68,69.97 U29.6
LED1: length 60.1
  TOP w0.127: J23.6 47.37,36.96 47.24,36.83 43.72,36.83 33.44,47.11 11.41,47.11 5.48,53.04 2.49,53.04 2.03,53.49 2.03,58.8 J37.8
LED2: length 56.1
  TOP w0.127: J37.9 5.84,54.58 5.84,53.03 11.51,47.36 33.55,47.36 39.76,41.15 46.67,41.15 48.13,39.69 48.9,39.69 49.87,38.72 J23.16
M2_3.3V: length 291.2
  TOP w0.203: C23.1 72.94,43.73 U11.3
  TOP w0.381: v1(33.22,10.68) 33.22,9.49 R58.1 ; R38.1 88.46,12.74 v1(87.6,12.74) ; R25.1 v1(87.6,15.36) ; v1(32.92,12.6) 20.44,12.6 18.75,14.3 v1(18.75,19.89)
  TOP w0.508: v1(78.05,44.37) 78.03,44.4 78.03,45.09 78.69,45.75 78.69,60.66 80.25,62.21 v1(82.83,62.21) ; v1(78.05,44.37) 80.8,44.37 81.43,43.74 v1(81.43,42.72) ; v1(78.05,44.37) 74.9,44.37 74.34,43.81 C23.1 ; v1(87.6,15.36) 87.6,17.15 87.1,17.65 87.1,21.79 v1(86.72,22.17) ; v1(88.32,26.95) 88.6,26.95 90.17,28.52 91.16,28.52 J21.1 ; v1(87.6,12.74) 87.6,12.18 88.66,11.11 R27.2
  L03_PWR w0.508: v1(78.05,44.37) 75.08,44.37 74.17,43.46 70.51,43.46 70,43.97 68.05,43.97 66.88,45.14 41.86,45.14 ; J21.1 92.81,31.25 92.08,31.98 87.02,31.98 85.75,33.25 82.4,33.25 81.43,34.21 v1(81.43,42.72)
  L03_PWR w0.635: v1(38.81,28.4) 38.81,41.18 38.92,41.28 38.92,42.19 41.86,45.14
  BOTTOM w0.381: 21.63,21.75 C33.1 21.1,22.3 ; v1(32.92,12.6) 33.58,12.6 SW5.2 ; 25.2,22.3 C30.1 24.68,21.65 ; C31.1 23.66,21.65 ; C34.1 20.55,21.3 ; C34.1 18.19,21.3 ; C34.1 19.37,20.37 ; C34.1 19.37,22.23 ; 22.52,16.29 L1.2 ; L1.2 23.98,19.12 ; L1.2 25.43,16.29 ; L1.2 23.98,13.46 ; C32.1 22.65,21.66
  BOTTOM w0.508: R70.2 v1(82.83,62.21) ; v1(86.72,22.17) 86.72,25.35 v1(88.32,26.95) ; v1(87.6,15.36) v1(87.6,12.74)
  BOTTOM w0.635: 17.6,21.29 13.77,21.29 9.25,25.81 9.25,42.32 5.16,46.41 5.16,75.59 J37.1 ; v1(38.81,28.4) 38.81,14.15 35.34,10.68 v1(33.22,10.68) 17.41,10.68 16.07,12.03 16.07,19.24 16.46,19.63 17.86,19.63
M2_GPIO1: length 76.7
  TOP w0.127: J23.59 60.62,44.04 59.41,42.82 47.53,42.82 47.35,43.01 44.04,43.01 37.01,50.04 32.89,50.04 28.17,54.76 28.17,58.32 26.21,60.27 22.63,60.27 19.76,63.14 13.8,63.14 6.12,70.82 6.12,73.74 4.76,75.1 J37.2
M2_GPIO2: length 75.9
  TOP w0.127: J37.3 4.73,72.56 5.16,72.14 5.16,69.97 5.77,69.36 7.23,69.36 13.77,62.81 19.58,62.81 22.38,60.02 26.11,60.02 27.91,58.21 27.91,54.58 33.41,49.09 37.59,49.09 43.93,42.75 47.24,42.75 47.42,42.57 59.59,42.57 61.12,44.1 J23.61
NEXTRST: length 80.1
  TOP w0.127: J10.100 111.1,28.14 v1(111.25,27.99) ; v1(95.28,26.9) 95.28,28.93 95.57,29.23 95.57,33.13 95.3,33.4 95.3,43.08 94.06,44.32 94.06,50.5 87.58,56.97 87.58,61.26 85.39,63.45 80.77,63.45 80.49,63.73 79.83,63.73 78.26,62.15 76.2,62.15 74.73,60.68 71.17,60.68 v1(70.94,60.45)
  BOTTOM w0.127: v1(111.25,27.99) 105.41,27.99 103.58,26.16 96.01,26.16 v1(95.28,26.9) ; U14.26 67.9,62.4 68.47,61.83 70.48,61.83 70.74,61.57 70.74,60.66 v1(70.94,60.45)
NLED_ACTIVITY: length 65.6
  TOP w0.203: J10.21 106.86,43.74 106.65,43.96 106.65,43.99 106.37,44.27 106.34,44.27 106.33,44.27 105.46,44.27 v1(105.27,44.46) ; v1(124.51,32.84) 124.51,28.07 132.74,19.84 132.74,16.61 135.38,13.97 136.63,13.97 139.47,11.13 139.47,6.41 R12.2
  BOTTOM w0.203: v1(105.27,44.46) 105.57,44.76 111.96,44.76 112.22,44.5 117.07,44.5 117.55,44.02 119.02,44.02 124.51,38.53 v1(124.51,32.84)
NOCS: length 27.3
  TOP w0.127: v1(64.47,67.86) 64.52,67.86 65.28,67.11 66.95,67.11 67.37,67.52 v1(68.58,67.52) 68.67,67.52 69.03,67.16 74.14,67.16 74.32,66.98 76.58,66.98 77.24,67.64 78.37,67.64 v1(78.79,67.22)
  BOTTOM w0.127: v1(68.58,67.52) 68.58,67.52 67.94,66.88 67.94,66.04 67.8,65.9 U14.19 ; v1(68.58,67.52) 68.64,67.46 68.64,65.72 67.82,64.9 U14.21 ; v1(68.58,67.52) 66.25,67.52 65.97,67.24 U14.17 ; U14.13 63.97,67.36 v1(64.47,67.86) ; v1(78.79,67.22) 79.03,66.98 U2.4
NPWR_LED: length 54.9
  TOP w0.203: U8.2 132.97,11.94 131.11,13.79 131.11,14.55 125.4,20.27 125.4,20.29 125.12,20.57 125.1,20.57 124.92,20.75 106.96,20.75 105.89,19.68 102.46,19.68 v1(101.22,18.44) ; v1(99.19,21.82) 99.19,22.5 101.73,25.04 105.26,25.04 105.87,25.65 105.87,28.19 106.62,28.94 J10.95
  BOTTOM w0.203: v1(101.22,18.44) 99.19,20.47 v1(99.19,21.82)
NRPIBOOT: length 22.6
  TOP w0.127: v1(104.8,25.88) 104.8,27.61 106.53,29.34 107.51,29.34 J10.93 ; SW8.5 v1(102.18,10.74)
  BOTTOM w0.127: v1(102.18,10.74) 102.18,21.11 104.8,23.72 v1(104.8,25.88)
PCIE_CLK_N: length 116.4
  TOP w0.127: v1(145.91,45.9) 145.64,46.16 145.56,46.16 145.21,45.82 144.75,45.82 144.74,45.81 144.65,45.81 144.58,45.74 J5.12 ; v1(58.61,50.29) 58.37,50.04 58.37,49.3 58.61,49.06 R47.2
  L05 w0.094: v1(58.61,50.29) 58.34,50.01 58.34,49.67 58.82,49.2 62.1,49.2 64.73,46.56 75.19,46.56 75.88,47.24 97.55,47.24 98.72,46.07 111.89,46.07 112.51,45.45 126,45.45 127.43,44.02 128.34,44.02 128.56,43.79 128.56,41.85 128.66,41.76 128.84,41.76 128.94,41.85 128.94,43.79 129.16,44.02 129.54,44.02 129.77,43.79 129.77,41.85 129.86,41.76 130.05,41.76 130.14,41.85 130.14,43.79 130.37,44.02 130.74,44.02 130.97,43.79 130.97,41.85 131.06,41.76 131.25,41.76 131.35,41.85 131.35,43.79 131.57,44.02 131.95,44.02 132.17,43.79 132.17,42 132.27,41.91 132.46,41.91 132.55,42 132.55,43.79 132.78,44.02 134.63,44.02 139.02,48.41 146.11,48.41 146.13,48.39 146.79,47.73 146.79,46.58 146.42,46.22 146.23,46.22 v1(145.91,45.9)
PCIE_CLK_NREQ_3P3: length 100.9
  TOP w0.14: J5.2 144.77,47.74 145.14,48.12 145.14,51.27 140.23,56.18 137.15,56.18 136.37,55.4 136.07,55.4 v1(136.02,55.35) ; v1(75.34,55.98) 75.34,55.93 74.7,55.29 74.7,52.53 72.37,50.19 67.21,50.19 66.39,51.02 61.38,51.02 60.34,49.98 60.03,49.98 59.59,49.53 R50.2
  BOTTOM w0.14: v1(75.34,55.98) 76.02,55.98 78.42,53.59 82.34,53.59 82.66,53.9 90.81,53.9 91.81,52.9 103.17,52.9 104.48,54.22 116.44,54.22 116.66,54.43 134.61,54.43 134.84,54.2 135.43,54.2 136.02,54.79 v1(136.02,55.35)
PCIE_CLK_P: length 116.3
  TOP w0.127: v1(57.78,50.29) 57.97,50.29 58.12,50.14 58.12,49.38 57.78,49.04 R46.2 ; J5.10 144.56,46.14 144.63,46.07 145.11,46.07 145.45,46.42 145.59,46.42 v1(145.91,46.74)
  L05 w0.094: v1(57.78,50.29) 57.79,50.29 58.12,49.96 58.12,49.58 58.72,48.97 62,48.97 64.64,46.33 75.29,46.33 75.97,47.02 97.46,47.02 98.63,45.85 111.8,45.85 112.41,45.23 125.9,45.23 127.34,43.79 128.24,43.79 128.34,43.7 128.34,41.76 128.56,41.53 128.94,41.53 129.16,41.76 129.16,43.7 129.26,43.79 129.45,43.79 129.54,43.7 129.54,41.76 129.77,41.53 130.14,41.53 130.37,41.76 130.37,43.7 130.46,43.79 130.65,43.79 130.74,43.7 130.74,41.76 130.97,41.53 131.35,41.53 131.57,41.76 131.57,43.7 131.67,43.79 131.85,43.79 131.95,43.7 131.95,41.91 132.17,41.68 132.55,41.68 132.78,41.91 132.78,43.7 132.87,43.79 134.72,43.79 139.11,48.18 146.01,48.18 146.56,47.63 146.56,46.68 146.33,46.45 146.08,46.45 145.91,46.62 v1(145.91,46.74)
PCIE_NRST_3P3: length 100.6
  TOP w0.14: v1(70.76,44.88) 70.76,42.09 72.11,40.74 72.11,37.49 73.1,36.5 73.1,33.12 72.2,32.22 R49.1 ; v1(134.65,53.64) 134.65,50.42 139.01,46.06 139.71,46.06 139.8,46.14 J5.9 ; v1(80.77,45.89) 80.77,52.15 v1(81.25,52.63)
  BOTTOM w0.14: v1(134.65,53.64) 134.25,54.04 131.36,54.04 131.14,53.82 104.65,53.82 103.33,52.51 91.65,52.51 90.65,53.51 84.11,53.51 83.01,52.4 82.14,52.4 81.92,52.63 v1(81.25,52.63) ; v1(70.76,44.88) 72.44,44.88 72.77,45.21 77.17,45.21 77.69,45.73 80.61,45.73 v1(80.77,45.89)
PCIE_PME_L: length 3.3
  TOP w0.14: J23.55 59.62,47.07 60.05,47.5 60.45,47.5 60.57,47.62 R51.1
PCIE_RX_N: length 116.5
  TOP w0.127: J5.18 144.59,44.54 144.65,44.6 145.34,44.6 145.47,44.48 146.07,44.48 v1(146.37,44.17) ; v1(56.96,52.03) 56.67,51.74 56.67,49.33 56.95,49.04 R43.2
  L05 w0.094: v1(146.37,44.17) 146.63,44.43 147.11,44.43 147.62,44.94 147.62,48.87 146.79,49.71 135.26,49.71 134.3,48.76 134.3,48.44 134.57,48.18 134.57,48.04 134.43,47.91 134.3,47.91 134.04,48.17 133.72,48.17 133.45,47.9 133.45,47.58 133.73,47.31 133.73,47.18 133.59,47.04 133.46,47.04 133.19,47.32 132.87,47.32 132.21,46.66 131.52,46.66 131.29,46.43 131.29,45.4 131.2,45.3 131.01,45.3 130.91,45.4 130.91,46.43 130.69,46.66 130.31,46.66 130.09,46.43 130.09,45.4 129.99,45.3 129.8,45.3 129.71,45.4 129.71,46.43 129.48,46.66 129.11,46.66 128.88,46.43 128.88,45.4 128.79,45.3 128.6,45.3 128.51,45.4 128.51,46.43 128.28,46.66 112.96,46.66 112.28,47.35 99.31,47.35 97.84,48.82 74.9,48.82 73.96,47.88 65.15,47.88 61.32,51.71 57.56,51.71 57.25,51.41 56.9,51.41 56.69,51.62 56.69,51.77 56.7,51.78 v1(56.96,52.03)
PCIE_RX_P: length 116.4
  TOP w0.127: v1(56.12,52.03) 56.41,51.74 56.41,49.35 56.12,49.06 R42.2 ; J5.16 144.59,44.94 144.65,44.88 145.45,44.88 145.61,44.73 146.28,44.73 146.37,44.82 v1(146.37,45.01)
  L05 w0.094: v1(146.37,45.01) 146.73,44.65 147.01,44.65 147.4,45.04 147.4,48.78 146.69,49.48 135.35,49.48 134.53,48.66 134.53,48.53 134.79,48.27 134.79,47.95 134.53,47.68 134.21,47.68 133.94,47.94 133.81,47.94 133.68,47.81 133.68,47.68 133.95,47.4 133.95,47.08 133.69,46.82 133.37,46.82 133.09,47.09 132.96,47.09 132.3,46.43 131.61,46.43 131.52,46.34 131.52,45.3 131.29,45.08 130.91,45.08 130.69,45.3 130.69,46.34 130.59,46.43 130.41,46.43 130.31,46.34 130.31,45.3 130.09,45.08 129.71,45.08 129.48,45.3 129.48,46.34 129.39,46.43 129.2,46.43 129.11,46.34 129.11,45.3 128.88,45.08 128.51,45.08 128.28,45.3 128.28,46.34 128.19,46.43 112.87,46.43 112.18,47.12 99.21,47.12 97.74,48.59 75,48.59 74.06,47.65 65.06,47.65 61.22,51.49 57.65,51.49 57.35,51.18 56.81,51.18 56.47,51.52 56.47,51.88 56.33,52.02 56.13,52.02 v1(56.12,52.03)
PCIE_TX_N: length 116.4
  TOP w0.127: R41.2 55.29,49.05 54.99,49.35 54.99,52.34 54.6,52.73 54.13,52.73 v1(53.95,52.91) ; v1(146.57,42.14) 146.37,42.34 146.15,42.34 145.06,43.43 144.76,43.43 144.74,43.41 144.63,43.41 144.56,43.34 J5.24
  L05 w0.094: v1(53.95,52.91) 54.18,52.68 54.62,52.68 55.33,53.39 57.78,53.39 58.16,53.01 61.94,53.01 65.5,49.45 72.8,49.45 73.45,50.11 98.8,50.11 100.34,48.56 113.36,48.56 113.97,47.95 131.67,47.95 134.64,50.93 147.15,50.93 148.51,49.56 148.51,42.75 148.13,42.37 146.81,42.37 v1(146.57,42.14)
PCIE_TX_P: length 116.5
  TOP w0.127: R40.2 54.47,49.03 54.74,49.3 54.74,52.2 54.48,52.45 54.03,52.45 53.95,52.37 v1(53.95,52.07) ; J5.22 144.57,43.74 144.63,43.68 145.17,43.68 146.23,42.62 146.46,42.62 146.57,42.74 v1(146.57,42.97)
  L05 w0.094: v1(146.57,42.97) 146.57,42.69 146.67,42.6 148.04,42.6 148.29,42.84 148.29,43.12 148.16,43.26 148.16,43.54 148.29,43.67 148.29,43.95 148.16,44.08 148.16,44.37 148.29,44.5 148.29,49.47 147.05,50.7 145.82,50.7 145.68,50.57 145.4,50.57 145.27,50.7 141.22,50.7 141.09,50.57 140.8,50.57 140.67,50.7 134.73,50.7 131.76,47.73 113.88,47.73 113.27,48.34 100.25,48.34 98.7,49.89 73.55,49.89 72.89,49.23 65.4,49.23 61.85,52.78 58.06,52.78 57.68,53.16 55.42,53.16 54.71,52.45 54.04,52.45 53.95,52.36 v1(53.95,52.07)
PERI_5V: length 37.1
  TOP w0.508: v1(87.68,77.47) 87.68,73.36 83.05,68.73 v1(83.05,64.77)
  BOTTOM w0.381: 136.98,79.96 U4.1 ; U4.1 137.66,80.69 ; U4.1 136.98,81.42 ; 25.64,63.9 D27.C ; D27.C 26.62,65.23 ; D27.C 24.66,65.23 ; D27.C 25.64,66.56 ; J9.2 151.65,69.65 ; J9.2 152.91,68.39 ; J9.2 150.4,68.39 ; 134.98,79.92 C17.1 136.04,79.92 ; D28.C 26.62,60.78 ; D28.C 25.64,62.11 ; D28.C 24.66,60.78 ; D28.C 25.64,59.45
  BOTTOM w0.508: C17.1 135.51,80.61 135.59,80.69 U4.1 ; v1(83.05,64.77) 83.05,63.84 82.47,63.25 C1.1 81.68,63.26 U2.1
  vias: v1(25.1,63.14) v1(26.16,63.09) v1(27.23,64.24) v1(27.2,62.03) v1(27.28,63.09) v1(108.13,82.12) v1(108.13,80.82) v1(108.15,83.41) v1(109.12,82.78) v1(109.14,81.53)
PWM0_0: length 34
  TOP w0.14: v1(85.9,34.42) 88.11,36.63 v1(88.11,38.33) ; v1(73.96,19.89) 75.04,19.89 84.37,29.21 85.78,29.21 86.41,29.84 86.41,31.13 88.94,33.66 v1(89.51,33.66)
  BOTTOM w0.14: v1(85.9,34.42) 85.9,34.42 86.66,33.66 v1(89.51,33.66) ; R82.1 72.88,19.89 v1(73.96,19.89) ; R87.2 v1(88.11,38.33)
PWM0_1: length 44.3
  TOP w0.14: v1(70.04,20.79) 75.39,20.79 84.2,29.6 84.21,29.6 88.71,34.1 91,34.1 91.54,34.65 v1(91.54,44.6)
  BOTTOM w0.14: R89.1 87.15,44.15 88.29,44.15 88.75,44.6 v1(91.54,44.6) ; R83.1 v1(70.04,20.79)
PWR1: length 20.3
  TOP w0.508: v1(79.12,65.71) 78.32,65.71 77.41,64.8 72.52,64.8 71.63,65.68 65.1,65.68 63.71,67.07 v1(63.71,67.97)
  BOTTOM w0.305: U14.12 63.47,67.56 63.71,67.81 v1(63.71,67.97)
  BOTTOM w0.508: v1(79.12,65.71) 79.12,65.38 U2.3
RTS: length 126.1
  TOP w0.127: R97.2 71.55,35.46 v1(71.55,34.92)
  L04 w0.127: v1(71.55,34.92) 69.7,34.92 69.37,34.59 69.37,30.05 67.74,28.43 41.8,28.43 40.63,27.26 36.11,27.26 35.33,26.47 28.99,26.47 27.95,27.51 16,27.51 13.16,30.35 13.16,59.13 16.07,62.05 16.07,62.06 20.74,66.73 20.74,75.31 23.46,78.03 23.46,80.91 24.51,81.96 v1(24.51,83.16)
  BOTTOM w0.14: U16.21 v1(24.51,83.16)
RUN_PG: length 48.6
  TOP w0.127: v1(105.99,10.74) SW8.2 ; v1(112.85,29.01) 112.52,29.34 111.28,29.34 110.87,29.74 J10.92
  BOTTOM w0.127: v1(105.99,10.74) 104.78,11.96 104.78,19.74 108.03,22.99 108.03,25.43 107.62,25.83 106.38,25.83 106.08,26.13 106.08,27.29 106.27,27.48 112.29,27.48 112.85,28.04 v1(112.85,29.01) 112.11,29.01 111.9,29.21 106.76,29.21 106.43,28.88 103.86,28.88 103.56,29.18 102.08,29.18 101.48,28.59 98.74,28.59 98.34,28.99 J49.1
RXD: length 148.3
  TOP w0.14: v1(77.9,30.68) 78.28,30.3 79.02,30.3 82.96,34.24 82.96,34.49 83.98,35.52 83.98,36.11 83.59,36.5 83.59,38.46 83.66,38.52 83.66,38.89 83.59,38.96 v1(83.59,41.53)
  L04 w0.112: v1(77.9,30.68) 77.27,30.05 74.98,30.05 72.62,27.69 69.01,27.69 68.76,27.43 42.21,27.43 41.05,26.26 36.53,26.26 35.74,25.48 28.57,25.48 27.53,26.52 15.42,26.52 11.98,29.96 11.98,59.58 19.41,67.01 19.41,75.79 22.28,78.66 22.28,81.64 22.81,82.17 22.81,84.71 23.56,85.46 v1(25.15,85.46)
  BOTTOM w0.14: U16.1 v1(25.15,85.46) ; R95.2 v1(83.59,41.53)
SCL0: length 71.3
  TOP w0.14: J10.80 111.44,32.14 111.68,32.38 114.35,32.38 v1(114.96,31.78) ; v1(118.67,32.41) 121.08,32.41 122.31,33.63 123.78,33.63 123.78,33.63 124.12,33.63 128.88,38.38 128.88,73.54 129.94,74.6 131.68,74.6 133.53,72.75 140.72,72.75 140.92,72.54 U3.2
  L04 w0.112: v1(118.67,32.41) 118.03,31.78 v1(114.96,31.78)
